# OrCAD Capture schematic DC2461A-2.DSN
size A
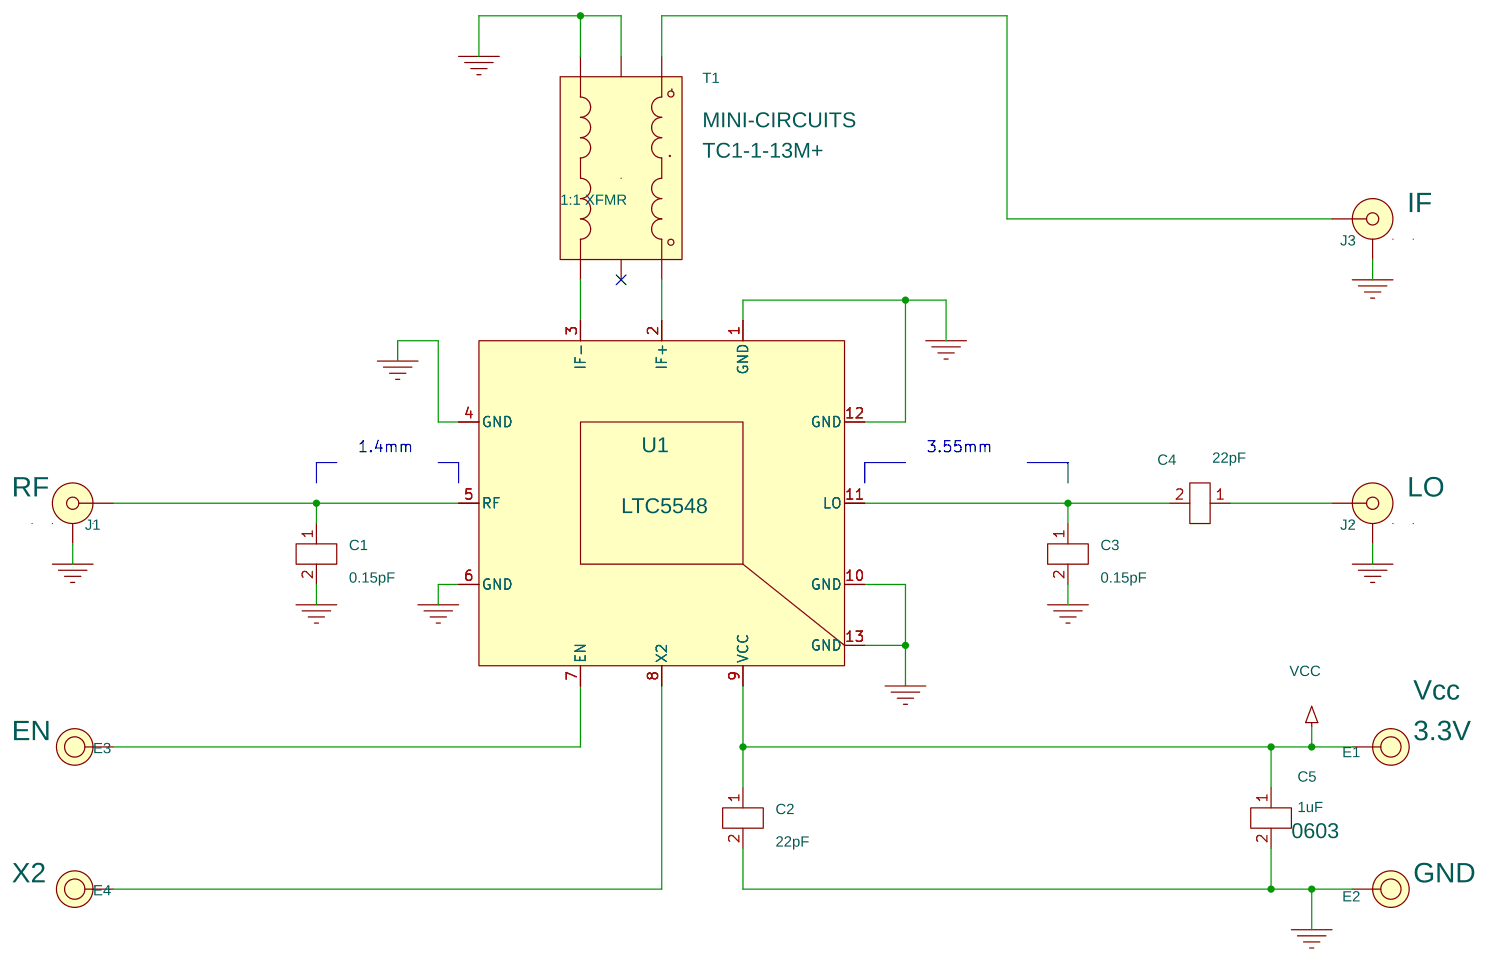
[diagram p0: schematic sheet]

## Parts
C1  0.15pF  [0402_(1005)]
C2  22pF  [0402-SEAN]
C3  0.15pF  [0402_(1005)]
C4  22pF  [0402_(1005)]
C5  1uF  [0603-SEAN]
E1  Vcc  [MILLMAX2308]
E2  GND  [MILLMAX2308]
E3  EN  [MILLMAX2308]
E4  X2  [MILLMAX2308]
J1  RF  [CON\SMA-END]
J2  LO  [CON\SMA-END]
J3  IF  [CON\SMA-END]
T1  1:1 XFMR  [TRANS-TC1-1-13M+]
U1  LTC5548

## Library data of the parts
C1-C4 = DNI_0
C5 = DNI_1: 1: 0603
E1-E4 = Small_Turret: VOLTAGE: 3.3V
J1-J3 = CON_SMA-END_3: CONN, BNC, SMA 50-OHM EDGE-LANCH; 1 FILD: 50 Ohm; 2 FILD: 30MHz-3000MHz; Part Number: E.F.JOHNSON, 142-0701-851
T1 = TRANS-LDB319_1: 4TH PART FIELD: MINI-CIRCUITS; 5TH PART FIELD: TC1-1-13M+
U1 = LTC5548

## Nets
GND: C1.2 C2.2 C3.2 C5.2 E2.1 J1.2(GND) J1.3(GND) J1.4(GND) J1.5(GND) J2.2(GND) J2.3(GND) J2.4(GND) J2.5(GND) J3.2(GND) J3.3(GND) J3.4(GND) J3.5(GND) T1.4 T1.5 U1.1(GND) U1.4(GND) U1.6(GND) U1.10(GND) U1.12(GND) U1.13(GND)
VCC: C2.1 C5.1 E1.1 U1.9(VCC)
N00666: C1.1 J1.1(CENTER) U1.5(RF)
N16714810: J3.1(CENTER) T1.6
N16715096: C4.1 J2.1(CENTER)
N16715129: C3.1 C4.2 U1.11(LO)
N16716788: E3.1 U1.7(EN)
N16716797: E4.1 U1.8(X2)
N16722309: T1.3 U1.3(IF-)
N16722313: T1.1 U1.2(IF+)

Not connected (* = marked no-connect by the designer): T1 2*

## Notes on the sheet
- 1.4mm
- 3.55mm
